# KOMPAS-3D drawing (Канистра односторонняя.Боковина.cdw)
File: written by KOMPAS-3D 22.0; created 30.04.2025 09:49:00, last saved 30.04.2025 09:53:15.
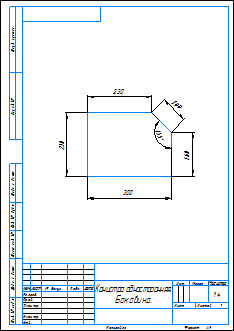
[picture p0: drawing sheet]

Sheet 1: A4, portrait

Document properties: Автор: Admin; Наименование: Канистра односторонняя. Боковина

Title block, sheet 1: Наименование: Канистра односторонняя. / Боковина.; scale: 1:4; Количество листов документа: 1; Форматы листов документа: A4; stored path: D:\28.11.2016\3D модели\Абилимпикс\2025\Канистра односторонняя\Канистра односторонняя.Боковина.cdw

Dimensions and other numbers on the sheet: 230; 300; 100; 160; 135; 1:4; 1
